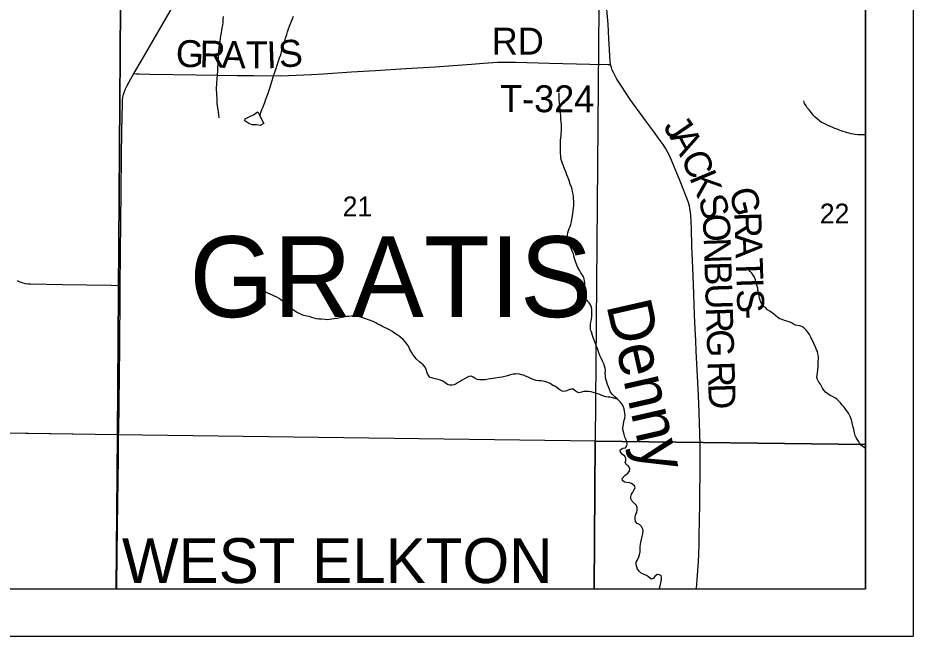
# Model space of a CAD drawing. Extents: x -8.8 to 41.4, y 0 to 34.6.
# Drawn here: x 7.113 to 9, y 14 to 15.304 of the extents above; entities that cross this region are included whole.
import ezdxf

# ---------------------------------------------------------------- set-up
doc = ezdxf.new("R2010")
doc.units = 0
for name, color, linetype in [('GM_X_Corporation', 7, 'Continuous'), ('GM_X_County_Road', 7, 'Continuous'), ('GM_X_Minor_River', 7, 'Continuous'), ('GM_X_Minor_River_Text', 7, 'Continuous'), ('GM_X_Section_Text', 7, 'Continuous'), ('GM_X_State_Location', 7, 'Continuous'), ('GM_X_State_Route', 7, 'Continuous'), ('GM_X_Township_Road', 7, 'Continuous'), ('GM_X_Township_Text', 7, 'Continuous'), ('GM_X_Unincorporated', 7, 'Continuous'), ('SH_Border', 7, 'Continuous')]:
    doc.layers.add(name, color=color, linetype=linetype)

msp = doc.modelspace()

# ---------------------------------------------------------------- linework, layer by layer
at = {"layer": 'GM_X_Corporation'}
msp.add_lwpolyline([(5.3614, 17.3836), (5.3531, 16.5483), (5.3461, 16.3507), (5.3393, 15.3164), (5.3375, 15.0446), (5.3339, 14.5882), (5.3314, 14.2618), (5.3311, 14.2265), (5.3301, 14.1), (8.9, 14.1), (8.9, 18.5906)], dxfattribs=at)
for points in [[(6.3374, 15.4422), (7.3307, 15.4293), (7.3236, 14.4245), (6.336, 14.4395)], [(7.3307, 15.4293), (8.3386, 15.4097), (8.3298, 14.411), (7.3236, 14.4245)], [(8.9, 14.4042), (8.9, 15.4006), (8.3386, 15.4097), (8.3298, 14.411)], [(6.3313, 14.1), (7.3207, 14.1), (7.3236, 14.4245), (6.336, 14.4395)], [(6.8296, 14.1), (7.3217, 14.1), (7.3218, 14.1076), (7.3234, 14.2324), (7.3251, 14.3764), (7.3255, 14.4247), (6.8363, 14.4315)], [(7.3207, 14.1), (8.328, 14.1), (8.3298, 14.411), (7.3236, 14.4245)], [(8.328, 14.1), (8.9, 14.1), (8.9, 14.4042), (8.3298, 14.411)]]:
    msp.add_lwpolyline(points, close=True, dxfattribs=at)
at = {"layer": 'GM_X_County_Road'}
msp.add_lwpolyline([(7.3292, 14.7387), (7.3233, 14.7389), (7.3102, 14.7393), (7.2084, 14.741), (7.1401, 14.742), (7.1351, 14.7423), (7.1297, 14.7431), (7.1242, 14.7445), (7.1208, 14.7456), (7.118, 14.7466), (7.1151, 14.7478), (7.1125, 14.7492)], dxfattribs=at)
at = {"layer": 'GM_X_Minor_River'}
for points in [[(7.5461, 15.3068), (7.5455, 15.3), (7.545, 15.294), (7.5444, 15.2887), (7.5431, 15.2826), (7.5426, 15.2777), (7.5417, 15.272), (7.5407, 15.2656), (7.5398, 15.2599), (7.5389, 15.2542), (7.5375, 15.2463), (7.537, 15.2414), (7.5361, 15.2349), (7.5355, 15.2266), (7.5353, 15.2201), (7.5347, 15.2148), (7.534, 15.1901), (7.5335, 15.1852), (7.5324, 15.1739), (7.5323, 15.1685), (7.5321, 15.1632), (7.5316, 15.1568), (7.5314, 15.1515), (7.5317, 15.1461), (7.5319, 15.14), (7.5325, 15.1347), (7.5329, 15.1233), (7.5335, 15.1183), (7.5348, 15.1103), (7.5354, 15.1046), (7.536, 15.0997), (7.5366, 15.0932)], [(7.6234, 15.0974), (7.6239, 15.0991), (7.6256, 15.1043), (7.6277, 15.1103), (7.6297, 15.1145), (7.6338, 15.125), (7.6355, 15.1299), (7.6376, 15.1359), (7.6401, 15.1426), (7.6421, 15.149), (7.6446, 15.1554), (7.6493, 15.172), (7.6522, 15.1814), (7.6551, 15.1893), (7.6576, 15.1968), (7.6597, 15.2043), (7.6623, 15.2122), (7.6648, 15.2194), (7.6672, 15.2258), (7.6706, 15.2378), (7.6727, 15.2442), (7.674, 15.2495), (7.6757, 15.254), (7.6766, 15.2585), (7.6778, 15.2634), (7.6799, 15.2687), (7.6816, 15.2743), (7.6837, 15.2803), (7.6861, 15.286), (7.6902, 15.2965), (7.6919, 15.3014), (7.694, 15.307)], [(8.3076, 14.749), (8.3066, 14.7536), (8.3046, 14.759), (8.3, 14.7663), (8.2968, 14.7717), (8.2932, 14.7772), (8.2911, 14.7822), (8.2884, 14.7898), (8.2864, 14.7964), (8.285, 14.801), (8.2841, 14.8059), (8.2817, 14.8121), (8.28, 14.8163), (8.2768, 14.8236), (8.2748, 14.829), (8.2731, 14.8352), (8.2718, 14.8413), (8.272, 14.8462), (8.2725, 14.8504), (8.2735, 14.8553), (8.2751, 14.8594), (8.2771, 14.8636), (8.2788, 14.8681), (8.2801, 14.8734), (8.2811, 14.8783), (8.2816, 14.8825), (8.283, 14.8904), (8.2836, 14.8976), (8.2842, 14.9025), (8.2848, 14.9082), (8.2849, 14.9132), (8.2847, 14.9181), (8.2845, 14.9223), (8.284, 14.9276), (8.2834, 14.9318), (8.2821, 14.9376), (8.2815, 14.9418), (8.2798, 14.9468), (8.2773, 14.9529), (8.275, 14.961), (8.2726, 14.9675), (8.2705, 14.9729), (8.2681, 14.9794), (8.266, 14.9837), (8.2613, 14.9968), (8.2592, 15.0029), (8.2579, 15.0079), (8.2573, 15.0132), (8.2567, 15.0174), (8.2566, 15.0235), (8.2567, 15.0281), (8.2566, 15.0334), (8.257, 15.0459), (8.2575, 15.0505), (8.2581, 15.0558), (8.2583, 15.0604), (8.2588, 15.0645), (8.2592, 15.0748), (8.2589, 15.079), (8.2584, 15.0835), (8.2578, 15.0893), (8.2576, 15.0946), (8.2569, 15.1072), (8.256, 15.1118), (8.2558, 15.116), (8.2546, 15.1259), (8.254, 15.1305), (8.2538, 15.1354), (8.2542, 15.1449)], [(8.9, 15.0568), (8.8969, 15.0572), (8.8928, 15.0573), (8.8887, 15.057), (8.8838, 15.0572), (8.8782, 15.0577), (8.8737, 15.0582), (8.8696, 15.0591), (8.8647, 15.0608), (8.8595, 15.0621), (8.8506, 15.0646), (8.8465, 15.0662), (8.8402, 15.0687), (8.835, 15.0707), (8.8306, 15.0728), (8.8247, 15.0752), (8.8206, 15.0769), (8.8154, 15.0797), (8.8114, 15.0817), (8.8073, 15.0833), (8.8025, 15.0865), (8.7978, 15.0905), (8.7938, 15.094), (8.7894, 15.0987), (8.7862, 15.1033), (8.7812, 15.1096), (8.7768, 15.1139), (8.7744, 15.1185), (8.7712, 15.1235), (8.7695, 15.1285)], [(7.6234, 15.0974), (7.6315, 15.081), (7.6242, 15.0771), (7.6163, 15.0784), (7.6071, 15.0779), (7.6004, 15.0812), (7.5956, 15.0836), (7.5918, 15.0864), (7.5927, 15.0905), (7.602, 15.096), (7.6097, 15.0991), (7.6155, 15.1035)], [(7.6155, 15.1035), (7.6192, 15.1054)], [(7.6192, 15.1054), (7.6234, 15.0974)], [(8.6739, 14.7248), (8.6729, 14.7298), (8.6726, 14.734), (8.6716, 14.7378), (8.6688, 14.747), (8.6678, 14.7516), (8.6661, 14.7566), (8.6602, 14.7651), (8.6566, 14.769), (8.6529, 14.7733)], [(8.4175, 14.2609), (8.4188, 14.2666), (8.4182, 14.2712), (8.4169, 14.2754), (8.4118, 14.2808), (8.4075, 14.2852), (8.405, 14.2898), (8.4048, 14.294), (8.4065, 14.2993), (8.4092, 14.3034), (8.4117, 14.3079), (8.4141, 14.3127), (8.4127, 14.3169), (8.4069, 14.3217), (8.4021, 14.3233), (8.3968, 14.3239), (8.3916, 14.3248), (8.3876, 14.3279), (8.387, 14.3325), (8.3925, 14.3384), (8.3983, 14.3432), (8.4022, 14.3481), (8.4028, 14.3534), (8.4003, 14.358), (8.3959, 14.3612), (8.3934, 14.3658), (8.3944, 14.3703), (8.3949, 14.3745), (8.3924, 14.3791), (8.3873, 14.3827), (8.3837, 14.3878), (8.3828, 14.3927), (8.3885, 14.396), (8.3938, 14.397), (8.397, 14.4011), (8.3975, 14.4056), (8.3969, 14.4098), (8.3956, 14.414), (8.3928, 14.4198), (8.3911, 14.4248), (8.3891, 14.4329), (8.3885, 14.4375), (8.3887, 14.4424), (8.3896, 14.4473), (8.3914, 14.4552), (8.3923, 14.4594), (8.3929, 14.4651), (8.3927, 14.47), (8.3921, 14.4742), (8.3908, 14.4796), (8.3887, 14.4846), (8.3863, 14.49), (8.3823, 14.4947), (8.3772, 14.4994), (8.3714, 14.5049), (8.3667, 14.5096), (8.3623, 14.5147), (8.3603, 14.52), (8.3578, 14.5254), (8.3561, 14.5304), (8.3548, 14.5354), (8.3535, 14.54), (8.3518, 14.5446), (8.3515, 14.5492), (8.3514, 14.5545), (8.3516, 14.5606), (8.351, 14.5648), (8.35, 14.5694), (8.3483, 14.574), (8.3455, 14.5798), (8.3423, 14.586), (8.3395, 14.5914), (8.3375, 14.5975), (8.3355, 14.6044), (8.3338, 14.6094), (8.3314, 14.6152), (8.3293, 14.6202), (8.3266, 14.6279), (8.3245, 14.634), (8.3222, 14.6417), (8.3204, 14.6459), (8.3199, 14.6509), (8.3201, 14.6577), (8.321, 14.6623), (8.322, 14.6676), (8.323, 14.6744), (8.3232, 14.6816), (8.3231, 14.6884), (8.3222, 14.6938), (8.3204, 14.6984), (8.3176, 14.7027), (8.3136, 14.7062), (8.3092, 14.7105), (8.3068, 14.7159), (8.3055, 14.7205), (8.3049, 14.7247), (8.3054, 14.73), (8.3071, 14.7353), (8.308, 14.7398), (8.3082, 14.7448), (8.3076, 14.749)], [(7.8807, 14.6536), (7.8767, 14.656), (7.8719, 14.6581), (7.8678, 14.6605), (7.8619, 14.6637), (7.8523, 14.667), (7.8448, 14.6695), (7.8404, 14.6712), (7.8352, 14.6728), (7.83, 14.6741), (7.8255, 14.6746), (7.8206, 14.6752), (7.8157, 14.6749), (7.8112, 14.6743), (7.8063, 14.6737), (7.8006, 14.6727), (7.7961, 14.6721), (7.7897, 14.6707), (7.7855, 14.6697), (7.7794, 14.6691), (7.7753, 14.6685), (7.7704, 14.6675), (7.7651, 14.6672), (7.761, 14.6674), (7.7524, 14.668), (7.7479, 14.6685), (7.743, 14.669), (7.7326, 14.6716), (7.7274, 14.6737), (7.7225, 14.6746), (7.7158, 14.6763), (7.7117, 14.6775), (7.7066, 14.68), (7.7025, 14.6816), (7.6985, 14.6844), (7.6941, 14.6876), (7.6897, 14.6903), (7.6849, 14.6943), (7.6769, 14.7014), (7.6722, 14.7057), (7.6678, 14.7092), (7.6638, 14.712), (7.6593, 14.7148), (7.6545, 14.7172), (7.6501, 14.7189), (7.6453, 14.7209), (7.6401, 14.7233), (7.6357, 14.7254), (7.6308, 14.7266)], [(8.9, 14.3956), (8.8968, 14.3978), (8.8916, 14.4022), (8.8872, 14.4069), (8.8847, 14.4111), (8.8821, 14.415), (8.88, 14.4188), (8.8782, 14.4227), (8.8764, 14.4284), (8.8751, 14.4361), (8.8738, 14.4407), (8.8717, 14.4498), (8.87, 14.4564), (8.8672, 14.4633), (8.8636, 14.4702), (8.8585, 14.4776), (8.8548, 14.4826), (8.8504, 14.4869), (8.8467, 14.4916), (8.8434, 14.4955), (8.839, 14.4998), (8.8353, 14.5026), (8.8304, 14.5054), (8.8252, 14.5074), (8.8203, 14.5106), (8.8155, 14.5145), (8.8119, 14.5188), (8.8093, 14.523), (8.8068, 14.5269), (8.8046, 14.5315), (8.8013, 14.5358), (8.7988, 14.5408), (8.7974, 14.5454), (8.7976, 14.55), (8.7985, 14.5549), (8.799, 14.5617), (8.7996, 14.5678), (8.8002, 14.5746), (8.8006, 14.5894), (8.7992, 14.5952), (8.7982, 14.6001), (8.7964, 14.604), (8.794, 14.6101), (8.7918, 14.6151), (8.79, 14.619), (8.7864, 14.6255), (8.7843, 14.6302), (8.7814, 14.6359), (8.7785, 14.6406), (8.7745, 14.6452), (8.77, 14.6499), (8.7656, 14.6527), (8.7611, 14.6544), (8.7565, 14.6549), (8.752, 14.6558), (8.7479, 14.6578), (8.7438, 14.6605), (8.7385, 14.663), (8.734, 14.6642), (8.7291, 14.6655), (8.7239, 14.6676), (8.7194, 14.6688), (8.7156, 14.6712), (8.7104, 14.6752), (8.7034, 14.6811), (8.6982, 14.6854), (8.6934, 14.6882), (8.6886, 14.6933), (8.6844, 14.6953), (8.6827, 14.6991), (8.679, 14.7042), (8.678, 14.7084), (8.6766, 14.7126), (8.6746, 14.721), (8.6739, 14.7248)], [(8.3772, 14.4994), (8.3616, 14.504), (8.3571, 14.5038), (8.3526, 14.5047), (8.3481, 14.5059), (8.3437, 14.5076), (8.3396, 14.5092), (8.3307, 14.5125), (8.3255, 14.5138), (8.3214, 14.5151), (8.3158, 14.516), (8.3109, 14.5161), (8.306, 14.5155), (8.3011, 14.5141), (8.2965, 14.5131), (8.2924, 14.5144), (8.288, 14.5175), (8.2833, 14.5207), (8.2788, 14.5209), (8.2746, 14.5195), (8.27, 14.5173), (8.265, 14.5155), (8.2606, 14.5164), (8.2554, 14.5196), (8.2496, 14.5236), (8.2452, 14.5268), (8.2407, 14.5288), (8.2348, 14.5324), (8.23, 14.5348), (8.226, 14.5361), (8.2207, 14.5374), (8.2163, 14.5383), (8.2114, 14.5384), (8.2058, 14.5393), (8.2017, 14.5402), (8.1957, 14.5423), (8.1887, 14.5459), (8.1832, 14.5483), (8.1791, 14.55), (8.1746, 14.5512), (8.1706, 14.5525), (8.1664, 14.553), (8.1623, 14.5527), (8.157, 14.5521), (8.1513, 14.5508), (8.1453, 14.549), (8.1396, 14.5477), (8.1343, 14.5463), (8.1286, 14.545), (8.1191, 14.5437), (8.1146, 14.5435), (8.1097, 14.5428), (8.1044, 14.5415), (8.0984, 14.5405), (8.0935, 14.5403), (8.0859, 14.5401), (8.0815, 14.5414), (8.0767, 14.5442), (8.0726, 14.5462), (8.0686, 14.5478), (8.064, 14.5476), (8.0598, 14.545), (8.0548, 14.5425), (8.0499, 14.5396), (8.0456, 14.5371), (8.0414, 14.5349), (8.0368, 14.532), (8.0326, 14.5302), (8.0281, 14.5292), (8.0236, 14.5294), (8.0187, 14.5306), (8.014, 14.5338), (8.0088, 14.5374), (8.004, 14.5398), (7.9992, 14.5411), (7.9925, 14.5428), (7.988, 14.5437), (7.9824, 14.545), (7.9781, 14.5501), (7.9756, 14.5551), (7.974, 14.562), (7.9719, 14.567), (7.9676, 14.572), (7.9603, 14.5776), (7.953, 14.5846), (7.9494, 14.5897), (7.9458, 14.594), (7.943, 14.599), (7.9395, 14.6044), (7.9363, 14.6114), (7.9306, 14.6199), (7.9255, 14.6254), (7.9212, 14.6293), (7.9168, 14.6328), (7.9128, 14.6352), (7.9072, 14.6388), (7.9018, 14.6432), (7.8966, 14.646), (7.8911, 14.6484), (7.8859, 14.6508), (7.8807, 14.6536)], [(8.4657, 14.1), (8.4659, 14.1013), (8.4668, 14.1062), (8.4682, 14.1123), (8.4695, 14.1191), (8.4701, 14.1236), (8.4691, 14.1278), (8.4646, 14.1291), (8.4605, 14.13), (8.4559, 14.1259), (8.4523, 14.1215), (8.4481, 14.1201), (8.4427, 14.1252), (8.4383, 14.1279), (8.4331, 14.1296), (8.4272, 14.1328), (8.4232, 14.136), (8.4192, 14.1414), (8.4175, 14.1457), (8.4162, 14.1506), (8.4167, 14.1556), (8.4188, 14.1597), (8.422, 14.1668), (8.4237, 14.1713), (8.4246, 14.1774), (8.4248, 14.1816), (8.425, 14.188), (8.4256, 14.1941), (8.427, 14.2009), (8.4284, 14.2073), (8.4302, 14.2157), (8.4308, 14.2225), (8.4298, 14.2271), (8.4273, 14.2313), (8.4233, 14.2353), (8.4185, 14.2373), (8.4153, 14.2416), (8.414, 14.2469), (8.4142, 14.2515), (8.4158, 14.2568), (8.4175, 14.2609)]]:
    msp.add_lwpolyline(points, dxfattribs=at)
at = {"layer": 'GM_X_State_Route'}
msp.add_line((7.3257, 14.4242), (7.3258, 14.4302), dxfattribs=at)
for points in [[(7.3258, 14.4302), (7.3279, 14.6094), (7.3291, 14.7243), (7.3292, 14.7387), (7.3304, 14.8746), (7.331, 14.9367), (7.3321, 15.0125), (7.3328, 15.0641), (7.3336, 15.1237), (7.334, 15.1305), (7.3348, 15.1365), (7.336, 15.1423), (7.3379, 15.1484), (7.3404, 15.1543), (7.3431, 15.1598), (7.3479, 15.1686), (7.3578, 15.1864), (7.3753, 15.216), (7.4423, 15.3315)], [(7.322, 14.1), (7.3221, 14.1071), (7.3236, 14.2318), (7.3253, 14.3758), (7.3257, 14.4242)]]:
    msp.add_lwpolyline(points, dxfattribs=at)
at = {"layer": 'GM_X_Township_Road'}
for points in [[(8.5436, 14.1), (8.5436, 14.1006), (8.5477, 14.1569), (8.5485, 14.173), (8.5491, 14.1935), (8.5493, 14.2109), (8.5505, 14.278), (8.5507, 14.3016), (8.5511, 14.3426), (8.5515, 14.4003), (8.5505, 14.4295), (8.5498, 14.4469), (8.5489, 14.4729), (8.5475, 14.5071), (8.5456, 14.548), (8.5443, 14.574), (8.5431, 14.6007), (8.5421, 14.6237), (8.5401, 14.6608), (8.5385, 14.6974), (8.5376, 14.7228), (8.5357, 14.7768), (8.534, 14.8221), (8.5327, 14.8594), (8.5321, 14.8737), (8.5313, 14.8886), (8.5305, 14.8972), (8.5297, 14.9021), (8.5287, 14.907), (8.5264, 14.9147), (8.5088, 14.9592), (8.4922, 15.0001), (8.4871, 15.012), (8.4826, 15.0209), (8.4779, 15.0291), (8.473, 15.0369), (8.4691, 15.0425), (8.4629, 15.051), (8.4548, 15.062), (8.4361, 15.0875), (8.404, 15.1318), (8.3852, 15.1595), (8.3759, 15.1742), (8.3711, 15.1829), (8.3683, 15.1884), (8.3661, 15.1935), (8.3642, 15.1988), (8.3628, 15.2036), (8.3626, 15.2051), (8.3621, 15.2078), (8.3616, 15.2115), (8.3591, 15.2599), (8.3572, 15.2908), (8.3525, 15.3458)], [(7.3578, 15.1864), (7.3636, 15.186), (7.3692, 15.1855), (7.3915, 15.185), (7.489, 15.1835), (7.5753, 15.182), (7.6101, 15.182), (7.6678, 15.1818), (7.7323, 15.1842), (7.757, 15.1855), (7.8167, 15.1901), (7.8668, 15.1929), (7.9313, 15.1967), (7.9927, 15.2007), (8.0695, 15.2062), (8.0949, 15.2085), (8.1243, 15.2101), (8.139, 15.2101), (8.1623, 15.2106), (8.2336, 15.208), (8.3185, 15.2062), (8.3574, 15.2052), (8.3626, 15.2051)]]:
    msp.add_lwpolyline(points, dxfattribs=at)
at = {"layer": 'SH_Border'}
for p, q in [((9, 21), (9, 14)), ((8.9, 20.9), (8.9, 14.1)), ((2.1, 14.1), (8.9, 14.1)), ((2, 14), (9, 14))]:
    msp.add_line(p, q, dxfattribs=at)

# ---------------------------------------------------------------- texts
at = {"layer": 'GM_X_Minor_River_Text'}
msp.add_text('Denny', height=0.09467, rotation=282.8389, dxfattribs=at).set_placement((8.3532, 14.6982))
at = {"layer": 'GM_X_Section_Text'}
for s, height, rotation, p in [('RD', 0.05682, 0, (8.1121, 15.2263)), ('G', 0.0568, 358.8306, (7.4459, 15.2005)), ('R', 0.0568, 358.829, (7.4959, 15.1994)), ('A', 0.0568, 358.8364, (7.5425, 15.1985)), ('T', 0.0568, 359.7279, (7.5935, 15.1975)), ('I', 0.0568, 2.1244, (7.6386, 15.1973)), ('S', 0.0568, 4.9908, (7.665, 15.1984)), ('T-324', 0.05682, 359.7186, (8.1295, 15.1053)), ('J', 0.0568, 304.4157, (8.4719, 15.0733)), ('A', 0.0568, 298.4462, (8.4862, 15.0527)), ('C', 0.0568, 293.1786, (8.5094, 15.01)), ('K', 0.0568, 292.6538, (8.5277, 14.9672)), ('G', 0.0568, 283.409, (8.612, 14.9392)), ('S', 0.0568, 286.1565, (8.5464, 14.9226)), ('O', 0.0568, 272.4943, (8.5565, 14.8894)), ('R', 0.0568, 271.8367, (8.6231, 14.8936)), ('N', 0.0568, 271.8089, (8.5587, 14.8396)), ('A', 0.0568, 271.8089, (8.6246, 14.847)), ('T', 0.0568, 271.811, (8.6262, 14.797)), ('B', 0.0568, 271.7683, (8.5602, 14.7896)), ('U', 0.0568, 271.7689, (8.5617, 14.743)), ('I', 0.0568, 271.8073, (8.6276, 14.7545)), ('S', 0.0568, 271.8099, (8.6283, 14.7312)), ('R', 0.0568, 271.7702, (8.5632, 14.693)), ('-', 0.0568, 271.8132, (8.6295, 14.6929)), ('G', 0.0568, 271.7689, (8.5647, 14.6463)), ('R', 0.0568, 271.7692, (8.5668, 14.5789)), ('D', 0.0568, 271.7693, (8.5682, 14.5322))]:
    msp.add_text(s, height=height, rotation=rotation, dxfattribs=at).set_placement(p)
at = {"layer": 'GM_X_State_Location'}
msp.add_text('GRATIS', height=0.17045, rotation=0, dxfattribs=at).set_placement((7.475, 14.6727))
at = {"layer": 'GM_X_Township_Text'}
for s, p in [('21', (7.7979, 14.8852)), ('22', (8.8034, 14.8702))]:
    msp.add_text(s, height=0.04186, rotation=0, dxfattribs=at).set_placement(p)
at = {"layer": 'GM_X_Unincorporated'}
msp.add_text('WEST ELKTON', height=0.094697, rotation=0, dxfattribs=at).set_placement((7.3326, 14.1118))

doc.saveas('drawing.dxf')
